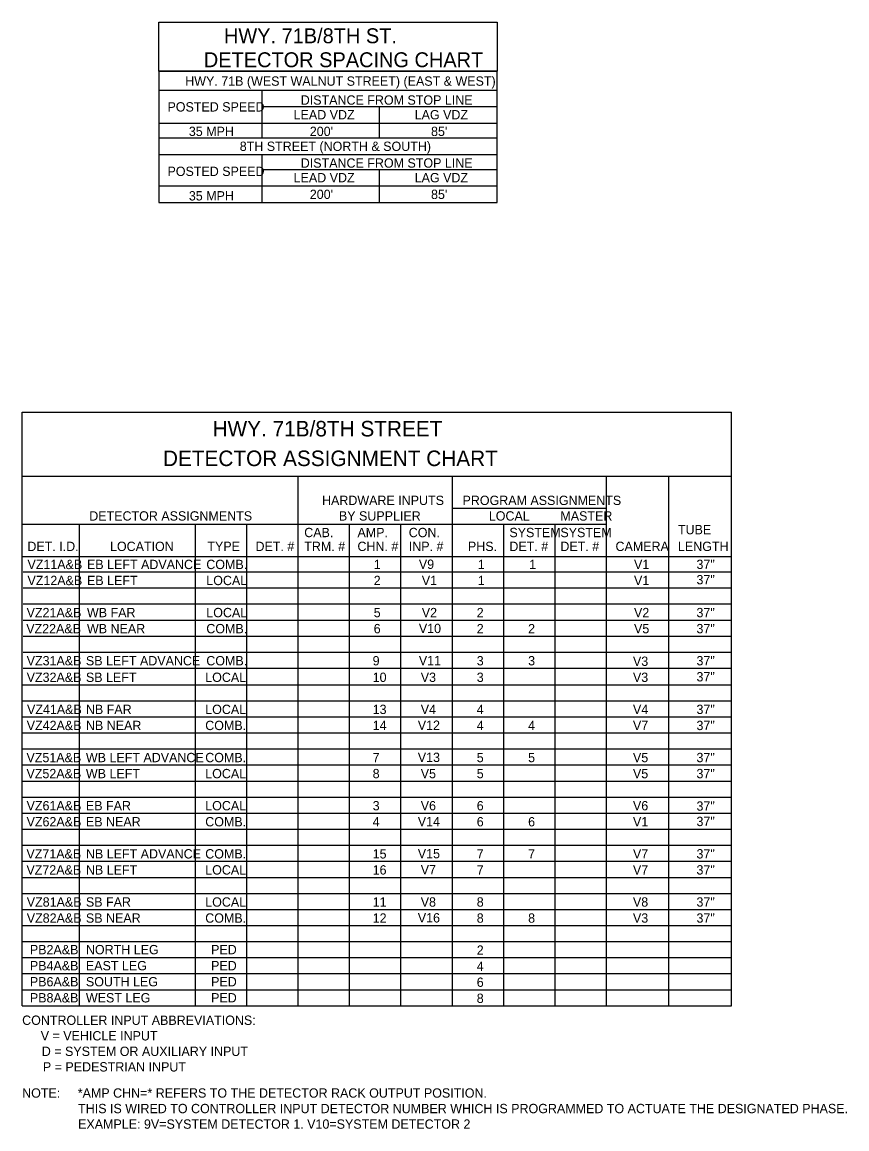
# Model space of a CAD drawing. Extents: x -19.5 to 29.5, y 0.4 to 10.6.
# Drawn here: x -19.46 to -12.39, y 0.71 to 10.21 of the extents above; entities that cross this region are included whole.
import ezdxf

# ---------------------------------------------------------------- set-up
doc = ezdxf.new("R2010")
doc.units = 0
for name, color, linetype in [('$', 7, 'Continuous'), ('base', 7, 'Continuous'), ('TBLBDR', 7, 'Continuous'), ('TBLLINE', 7, 'Continuous'), ('TBLTEXT', 7, 'Continuous'), ('TEXT', 7, 'Continuous'), ('TITEXT', 7, 'Continuous')]:
    doc.layers.add(name, color=color, linetype=linetype)

msp = doc.modelspace()

# ---------------------------------------------------------------- linework, layer by layer
at = {"layer": 'TBLBDR'}
for p, q in [((-18.292, 9.7836), (-18.292, 8.6581)), ((-18.292, 9.7836), (-15.3884, 9.7836)), ((-18.292, 9.7836), (-15.3884, 9.7836)), ((-15.3884, 8.6581), (-15.3884, 9.7836)), ((-18.292, 9.6208), (-15.3884, 9.6208)), ((-18.292, 9.2113), (-15.3884, 9.2113)), ((-18.292, 9.0676), (-15.3884, 9.0676)), ((-18.292, 8.6581), (-15.3884, 8.6581)), ((-19.464, 1.7635), (-19.464, 6.8586)), ((-19.464, 6.8586), (-13.3803, 6.8586)), ((-13.3803, 1.7635), (-13.3803, 6.8586)), ((-19.464, 6.3089), (-13.3803, 6.3089)), ((-17.0964, 1.7635), (-17.0964, 6.3089)), ((-15.7741, 1.7635), (-15.7741, 6.3089)), ((-14.4518, 1.7635), (-14.4518, 6.3089)), ((-13.916, 1.7635), (-13.916, 6.3089)), ((-15.7741, 6.0334), (-14.4518, 6.0334)), ((-19.464, 5.8957), (-14.4518, 5.8957)), ((-19.464, 5.6202), (-13.3803, 5.6202)), ((-19.464, 2.3144), (-13.3803, 2.3144)), ((-19.464, 1.7635), (-13.3803, 1.7635))]:
    msp.add_line(p, q, dxfattribs=at)
msp.add_lwpolyline([(-18.292, 10.205), (-15.3884, 10.205), (-15.3884, 9.7836), (-18.292, 9.7836)], close=True, dxfattribs=at)
at = {"layer": 'TBLLINE'}
for p, q in [((-17.4069, 9.6208), (-17.4069, 9.2113)), ((-17.4069, 9.4801), (-15.3884, 9.4801)), ((-16.3976, 9.2113), (-16.3976, 9.4801)), ((-18.292, 9.3393), (-15.3884, 9.3393)), ((-17.4069, 9.0676), (-17.4069, 8.6581)), ((-17.4069, 8.9396), (-16.3976, 8.9396)), ((-16.3976, 8.9396), (-15.3884, 8.9396)), ((-16.3976, 8.6581), (-16.3976, 8.9396)), ((-18.292, 8.7989), (-15.3884, 8.7989)), ((-18.971, 1.7635), (-18.971, 5.8957)), ((-17.9779, 1.7635), (-17.9779, 5.8957)), ((-17.5371, 1.7635), (-17.5371, 5.8957)), ((-16.6556, 1.7635), (-16.6556, 5.8957)), ((-16.2148, 1.7635), (-16.2148, 5.8957)), ((-15.3333, 1.7635), (-15.3333, 5.8957)), ((-14.8925, 1.7635), (-14.8925, 5.8957)), ((-19.4549, 5.4869), (-13.3803, 5.4869)), ((-19.4549, 5.3491), (-13.3803, 5.3491)), ((-19.4549, 5.2114), (-13.3803, 5.2114)), ((-19.4549, 5.0736), (-13.3803, 5.0736)), ((-19.4549, 4.9359), (-13.3803, 4.9359)), ((-19.4549, 4.7981), (-13.3803, 4.7981)), ((-19.4549, 4.6604), (-13.3803, 4.6604)), ((-19.464, 4.5183), (-13.3803, 4.5183)), ((-19.464, 4.3805), (-13.3803, 4.3805)), ((-19.464, 4.2428), (-13.3803, 4.2428)), ((-19.464, 4.105), (-13.3803, 4.105)), ((-19.464, 3.9673), (-13.3803, 3.9673)), ((-19.464, 3.8296), (-13.3803, 3.8296)), ((-19.464, 3.6918), (-13.3803, 3.6918)), ((-19.464, 3.5541), (-13.3803, 3.5541)), ((-19.464, 3.4163), (-13.3803, 3.4163)), ((-19.464, 3.2786), (-13.3803, 3.2786)), ((-19.464, 3.1409), (-13.3803, 3.1409)), ((-19.464, 3.0031), (-13.3803, 3.0031)), ((-19.464, 2.8654), (-13.3803, 2.8654)), ((-19.464, 2.7276), (-13.3803, 2.7276)), ((-19.464, 2.5899), (-13.3803, 2.5899)), ((-19.464, 2.4522), (-13.3803, 2.4522)), ((-19.464, 2.1767), (-13.3803, 2.1767)), ((-19.464, 2.0389), (-13.3803, 2.0389)), ((-19.464, 1.9012), (-13.3803, 1.9012))]:
    msp.add_line(p, q, dxfattribs=at)

# ---------------------------------------------------------------- texts
at = {"layer": '$'}
msp.add_text('HWY. 71B/8TH ST.', height=0.128, dxfattribs=at).set_placement((-17.7331, 10.0239))
at = {"layer": 'base'}
msp.add_text('DETECTOR SPACING CHART', height=0.128, dxfattribs=at).set_placement((-17.9056, 9.8181))
at = {"layer": 'TBLTEXT'}
for s, height, p in [('HWY. 71B (WEST WALNUT STREET) (EAST & WEST)', 0.08, (-18.0653, 9.6591)), ('POSTED SPEED', 0.08, (-18.2174, 9.4379)), ('DISTANCE FROM STOP LINE', 0.08, (-17.0742, 9.4964)), ('LEAD VDZ', 0.08, (-17.1354, 9.3705)), ('LAG VDZ', 0.08, (-16.0972, 9.3705)), ('35 MPH', 0.08, (-18.0342, 9.2276)), ("200'", 0.08, (-16.9967, 9.2276)), ("85'", 0.08, (-15.957, 9.2276)), ('8TH STREET (NORTH & SOUTH)', 0.08, (-17.5975, 9.0996)), ('DISTANCE FROM STOP LINE', 0.08, (-17.0742, 8.9559)), ('POSTED SPEED', 0.08, (-18.2174, 8.8847)), ('LEAD VDZ', 0.08, (-17.1354, 8.8301)), ('LAG VDZ', 0.08, (-16.0972, 8.8301)), ('35 MPH', 0.08, (-18.0342, 8.6744)), ("200'", 0.08, (-16.9967, 8.6871)), ("85'", 0.08, (-15.957, 8.6871)), ('HARDWARE INPUTS', 0.08, (-16.8919, 6.0608)), ('PROGRAM ASSIGNMENTS', 0.08, (-15.6869, 6.0608)), ('DETECTOR ASSIGNMENTS', 0.08, (-18.8883, 5.9272)), ('BY SUPPLIER', 0.08, (-16.747, 5.9272)), ('LOCAL', 0.08, (-15.4612, 5.9272)), ('MASTER', 0.08, (-14.8474, 5.9272)), ('TUBE', 0.08, (-13.839, 5.8096)), ('CAB.', 0.08, (-17.0446, 5.7848)), ('AMP.', 0.08, (-16.5879, 5.7848)), ('CON.', 0.08, (-16.1479, 5.7848)), ('SYSTEM', 0.08, (-15.2849, 5.7848)), ('SYSTEM', 0.08, (-14.8474, 5.7848)), ('DET. I.D.', 0.08, (-19.4194, 5.666)), ('LOCATION', 0.08, (-18.7106, 5.666)), ('TYPE', 0.08, (-17.8752, 5.666)), ('DET. #', 0.08, (-17.4625, 5.666)), ('TRM. #', 0.08, (-17.0446, 5.666)), ('CHN. #', 0.08, (-16.5879, 5.666)), ('INP. #', 0.08, (-16.1479, 5.666)), ('PHS.', 0.08, (-15.6403, 5.666)), ('DET. #', 0.08, (-15.2849, 5.666)), ('DET. #', 0.08, (-14.8474, 5.666)), ('CAMERA', 0.08, (-14.3747, 5.666)), ('LENGTH', 0.08, (-13.839, 5.666)), ('CONTROLLER INPUT ABBREVIATIONS:', 0.08, (-19.464, 1.5992)), ('V = VEHICLE INPUT', 0.08, (-19.3045, 1.4658)), ('D = SYSTEM OR AUXILIARY INPUT', 0.08, (-19.2954, 1.3325)), ('P = PEDESTRIAN INPUT', 0.08, (-19.2862, 1.1992)), ('NOTE:', 0.08, (-19.464, 0.9746)), ('*AMP CHN=* REFERS TO THE DETECTOR RACK OUTPUT POSITION.', 0.08, (-18.987, 0.9746)), ('THIS IS WIRED TO CONTROLLER INPUT DETECTOR NUMBER WHICH IS PROGRAMMED TO ACTUATE THE DESIGNATED PHASE.', 0.0799996, (-18.984, 0.8413)), ('EXAMPLE: 9V=SYSTEM DETECTOR 1. V10=SYSTEM DETECTOR 2', 0.08, (-18.984, 0.7079))]:
    msp.add_text(s, height=height, dxfattribs=at).set_placement(p)
at = {"layer": 'TEXT'}
for s, p in [('VZ11A&B', (-19.4184, 5.5109)), ('EB LEFT ADVANCE', (-18.9079, 5.5109)), ('COMB.', (-17.8845, 5.5109)), ('1', (-16.4485, 5.5109)), ('V9', (-16.0614, 5.5126)), ('1', (-15.5557, 5.5109)), ('1', (-15.115, 5.5109)), ('V1', (-14.2159, 5.5109)), ('37"', (-13.6802, 5.5117)), ('VZ12A&B', (-19.4184, 5.3732)), ('EB LEFT', (-18.9079, 5.3732)), ('LOCAL', (-17.8845, 5.3732)), ('2', (-16.4485, 5.3732)), ('V1', (-16.036, 5.3732)), ('1', (-15.5557, 5.3732)), ('V1', (-14.2159, 5.3732)), ('37"', (-13.6802, 5.3798)), ('VZ21A&B', (-19.4258, 5.0977)), ('WB FAR', (-18.9079, 5.0977)), ('LOCAL', (-17.8845, 5.0977)), ('5', (-16.4485, 5.0977)), ('V2', (-16.036, 5.0977)), ('2', (-15.5649, 5.0977)), ('V2', (-14.2159, 5.0977)), ('37"', (-13.6802, 5.0977)), ('VZ22A&B', (-19.4288, 4.96)), ('WB NEAR', (-18.9079, 4.96)), ('COMB.', (-17.8845, 4.96)), ('6', (-16.4485, 4.96)), ('V10', (-16.0614, 4.9617)), ('2', (-15.5649, 4.96)), ('2', (-15.1241, 4.96)), ('V5', (-14.2159, 4.96)), ('37"', (-13.6802, 4.96)), ('VZ31A&B', (-19.4252, 4.6845)), ('SB LEFT ADVANCE', (-18.917, 4.6845)), ('COMB.', (-17.8845, 4.6845)), ('9', (-16.4576, 4.6845)), ('V11', (-16.0614, 4.6862)), ('3', (-15.5649, 4.6845)), ('3', (-15.1241, 4.6845)), ('V3', (-14.225, 4.6801)), ('37"', (-13.6802, 4.6845)), ('VZ32A&B', (-19.4252, 4.5424)), ('SB LEFT', (-18.917, 4.5424)), ('LOCAL', (-17.8937, 4.5424)), ('10', (-16.4576, 4.5424)), ('V3', (-16.0452, 4.5424)), ('3', (-15.5649, 4.5424)), ('V3', (-14.225, 4.5424)), ('37"', (-13.6802, 4.5468)), ('VZ41A&B', (-19.4222, 4.2669)), ('NB FAR', (-18.917, 4.2669)), ('LOCAL', (-17.8937, 4.2669)), ('13', (-16.4576, 4.2669)), ('V4', (-16.0452, 4.2669)), ('4', (-15.5649, 4.2669)), ('V4', (-14.225, 4.2669)), ('37"', (-13.6802, 4.2669)), ('VZ42A&B', (-19.4249, 4.1291)), ('NB NEAR', (-18.917, 4.1291)), ('COMB.', (-17.8937, 4.1291)), ('14', (-16.4576, 4.1291)), ('V12', (-16.0705, 4.1308)), ('4', (-15.5649, 4.1291)), ('4', (-15.1241, 4.1291)), ('V7', (-14.225, 4.1291)), ('37"', (-13.6802, 4.1291)), ('VZ51A&B', (-19.4268, 3.8536)), ('WB LEFT ADVANCE', (-18.917, 3.8536)), ('COMB.', (-17.8937, 3.8536)), ('7', (-16.4576, 3.8536)), ('V13', (-16.0705, 3.8554)), ('5', (-15.5649, 3.8536)), ('5', (-15.1241, 3.8536)), ('V5', (-14.225, 3.8536)), ('37"', (-13.6802, 3.8536)), ('VZ52A&B', (-19.4268, 3.7159)), ('WB LEFT', (-18.917, 3.7159)), ('LOCAL', (-17.8937, 3.7159)), ('8', (-16.4576, 3.7159)), ('V5', (-16.0452, 3.7159)), ('5', (-15.5649, 3.7159)), ('V5', (-14.225, 3.7159)), ('37"', (-13.6802, 3.7159)), ('VZ61A&B', (-19.426, 3.4404)), ('EB FAR', (-18.917, 3.4404)), ('LOCAL', (-17.8937, 3.4404)), ('3', (-16.4576, 3.4404)), ('V6', (-16.0452, 3.4404)), ('6', (-15.5649, 3.4404)), ('V6', (-14.225, 3.4404)), ('37"', (-13.6802, 3.4372)), ('VZ62A&B', (-19.426, 3.3027)), ('EB NEAR', (-18.917, 3.3027)), ('COMB.', (-17.8937, 3.3027)), ('4', (-16.4576, 3.3027)), ('V14', (-16.0705, 3.3044)), ('6', (-15.5649, 3.3027)), ('6', (-15.1241, 3.3027)), ('V1', (-14.225, 3.3027)), ('37"', (-13.6802, 3.3052)), ('VZ71A&B', (-19.4272, 3.0272)), ('NB LEFT ADVANCE', (-18.917, 3.0272)), ('COMB.', (-17.8937, 3.0272)), ('15', (-16.4576, 3.0272)), ('V15', (-16.0705, 3.0289)), ('7', (-15.5649, 3.0272)), ('7', (-15.1241, 3.0272)), ('V7', (-14.225, 3.0272)), ('37"', (-13.6802, 3.0272)), ('VZ72A&B', (-19.4272, 2.8895)), ('NB LEFT', (-18.917, 2.8895)), ('LOCAL', (-17.8937, 2.8895)), ('16', (-16.4576, 2.8895)), ('V7', (-16.0452, 2.8912)), ('7', (-15.5649, 2.8895)), ('V7', (-14.225, 2.8895)), ('37"', (-13.6802, 2.8895)), ('VZ81A&B', (-19.4244, 2.614)), ('SB FAR', (-18.917, 2.614)), ('LOCAL', (-17.8937, 2.614)), ('11', (-16.4576, 2.614)), ('V8', (-16.0452, 2.614)), ('8', (-15.5649, 2.614)), ('V8', (-14.225, 2.614)), ('37"', (-13.6802, 2.614)), ('VZ82A&B', (-19.4244, 2.4762)), ('SB NEAR', (-18.917, 2.4762)), ('COMB.', (-17.8937, 2.4762)), ('12', (-16.4576, 2.4762)), ('V16', (-16.0705, 2.478)), ('8', (-15.5649, 2.4762)), ('8', (-15.1241, 2.4762)), ('V3', (-14.225, 2.4762)), ('37"', (-13.6802, 2.4762)), ('PB2A&B', (-19.3977, 2.2052)), ('NORTH LEG', (-18.917, 2.2052)), ('PED', (-17.8433, 2.2052)), ('2', (-15.5649, 2.2008)), ('PB4A&B', (-19.3977, 2.0674)), ('EAST LEG', (-18.917, 2.0674)), ('PED', (-17.8433, 2.0674)), ('4', (-15.5649, 2.063)), ('PB6A&B', (-19.3977, 1.9297)), ('SOUTH LEG', (-18.917, 1.9297)), ('PED', (-17.8433, 1.9297)), ('6', (-15.5649, 1.9253)), ('PB8A&B', (-19.3977, 1.7919)), ('WEST LEG', (-18.917, 1.7919)), ('PED', (-17.8433, 1.7919)), ('8', (-15.5649, 1.7875))]:
    msp.add_text(s, height=0.08, dxfattribs=at).set_placement(p)
at = {"layer": 'TITEXT'}
for s, p in [('HWY. 71B/8TH STREET', (-17.831, 6.6493)), ('DETECTOR ASSIGNMENT CHART', (-18.2564, 6.3949))]:
    msp.add_text(s, height=0.133333, dxfattribs=at).set_placement(p)

doc.saveas('drawing.dxf')
